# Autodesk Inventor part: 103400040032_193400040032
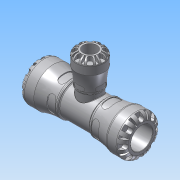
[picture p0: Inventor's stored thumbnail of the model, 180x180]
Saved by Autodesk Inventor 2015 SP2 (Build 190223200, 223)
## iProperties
Created: 2016-12
Part Number: 103400040032_193400040032
Material: PVC-Piping
Description: PLASSON REDUCING TEE 40X32X40 SERIES 1
Document SubType Name: Modeling
Designer: KIM
Mass: 664.223 g
Surface Area: 733.008 cm^2
Volume: 474.445 cm^3
Density: 1.4 g/cm^3
Appearance: Smooth - White
Author: KIM
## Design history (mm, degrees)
derived "1034.ipt"
feature "Solid1::1034.ipt"
tag "TaggingFeature1"
body "Solid1"
other parameters: "d230" = 58, "d232" = 9, "d1" = 29.4, "d8" = 59.5, "d13" = 8, "d14" = 8, "d15" = 0, "d17" = 360 deg, "d19" = 8 deg, "d20" = 0.8, "d21" = 0.8, "d22" = 8 deg, "d24" = 0, "d26" = 360 deg, "d33" = 7, "d43" = 54.6, "d51" = 0.7, "d54" = 14, "d55" = 8.8, "d57" = 15.68, "d58" = 0, "d74" = 0, "d77" = 3.33333, "d79" = 54.6, "d80" = 192, "d82" = 0.8, "d115" = 360 deg, "d139" = 8, "d140" = 0, "d142" = 360 deg, "d207" = 90 deg, "d209" = 22.68, "d210" = 32, "d212" = 58, "d213" = 49.3, "d215" = 45.24, "d216" = 2.66667, "d217" = 54, "d225" = 93, "d226" = 54, "d228" = 11.9, "d229" = 7.2, "d233" = 7.2, "d234" = 0, "d236" = 360 deg, "d238" = 8 deg, "d239" = 8 deg, "d240" = 0.8, "d241" = 0.8, "d243" = 0, "d245" = 360 deg, "d247" = 1.4, "d248" = 4.2, "d249" = 3.24, "d250" = 9.52, "d252" = 11.2, "d253" = 7.36, "d254" = 15.68, "d255" = 0, "d257" = 360 deg, "d259" = 0.8, "d261" = 0, "d262" = 1.4, "d264" = 0, "d266" = 0, "d267" = 0.7, "A_" = 93, "H_" = 192, "d_1" = 32, "E_1" = 58, "l_1" = 54
